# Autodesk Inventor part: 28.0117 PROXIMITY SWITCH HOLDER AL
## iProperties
Created: 2007-05
Part Number: 28.0117 PROXIMITY SWITCH HOLDER AL
Document SubType Name: Modeling
Designer: Andy Moles
Material: Aluminum-6061
Mass: 75.1573 g
Surface Area: 88.1781 cm^2
Volume: 27.7333 cm^3
Density: 2.71 g/cm^3
Author: Andy Moles
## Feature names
1. Extrusion1
